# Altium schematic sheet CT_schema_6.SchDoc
size 152 x 123 mm
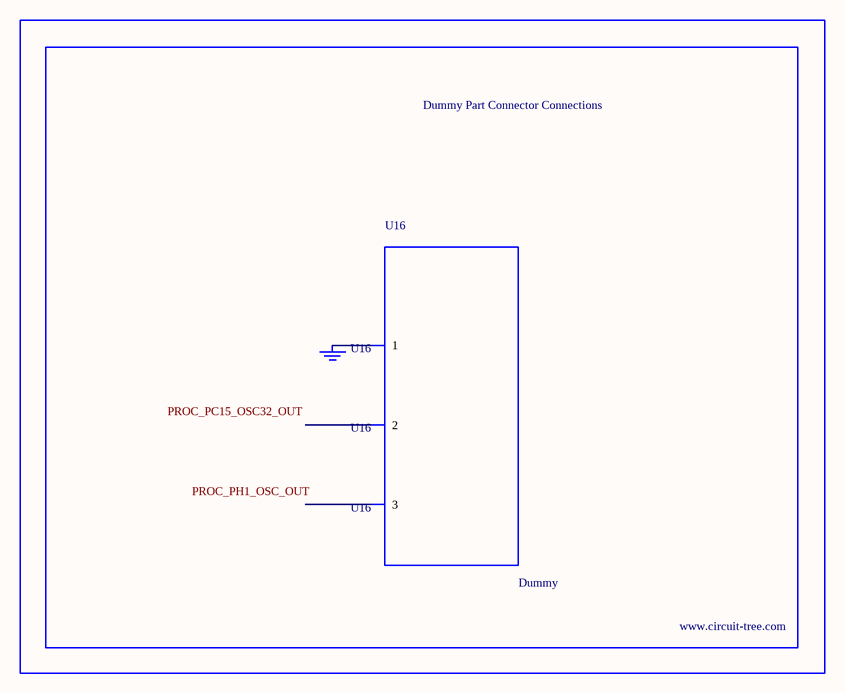
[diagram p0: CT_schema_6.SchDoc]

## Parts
BORDER5  (no value)
GND_INSTANCE_5_0  (no value)
U16  Dummy  [DUMMY_PACKAGE_140]

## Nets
NetGND_INSTANCE_5_0_0: GND_INSTANCE_5_0.0(GND) U16.1

Not connected (* = marked no-connect by the designer): U16 2 3

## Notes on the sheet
- Labels drawn without touching a wire or pin: PROC_PC15_OSC32_OUT, PROC_PH1_OSC_OUT

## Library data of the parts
BORDER5 = BORDER_PAGE5
GND_INSTANCE_5_0 = GND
